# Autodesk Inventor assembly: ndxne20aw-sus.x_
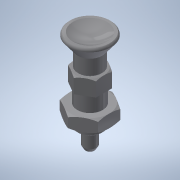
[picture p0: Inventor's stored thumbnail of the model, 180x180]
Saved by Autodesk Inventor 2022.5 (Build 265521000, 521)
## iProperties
Part Number: ndxne20aw-sus.x_
Material: 一般
Document SubType Name: Assembly
Designer: ImaoCorp
Sending System: SOLIDWORKS 2017-2017317
MC: AMD64
MC_MODEL: Intel64 Family 6 Model 60 Stepping 3, GenuineIntel
OS: Windows_NT
FRU: Parasolid Version 29.0, build 201,  4-17-2017
FORMAT: text
GUISE: transmit
KEY: ndxne20aw-sus
FILE: ndxne20aw-sus.x_t
DATE: Wed Sep 04 15:26:26 2019
Author: ImaoCorp
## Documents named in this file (3)
- X:\14_SW2022-Inv2022\00_全2023-1023新製品(TCC)まで\n\ndxne20aw-sus\NDXNE20AW-SUS.iam
- X:\14_SW2022-Inv2022\00_全2023-1023新製品(TCC)まで\n\ndxne20aw-sus\ndxne20aw-sus_01.ipt
- X:\14_SW2022-Inv2022\00_全2023-1023新製品(TCC)まで\n\ndxne20aw-sus\ndxne20aw-sus_02.ipt
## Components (2 placed, 2 different names)
1. ndxne20aw-sus_01
2. ndxne20aw-sus_02
